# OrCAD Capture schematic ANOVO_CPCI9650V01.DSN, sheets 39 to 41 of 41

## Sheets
39 -ON BOARD DDRII B1: size D; title: ON BOARD DDRII B1
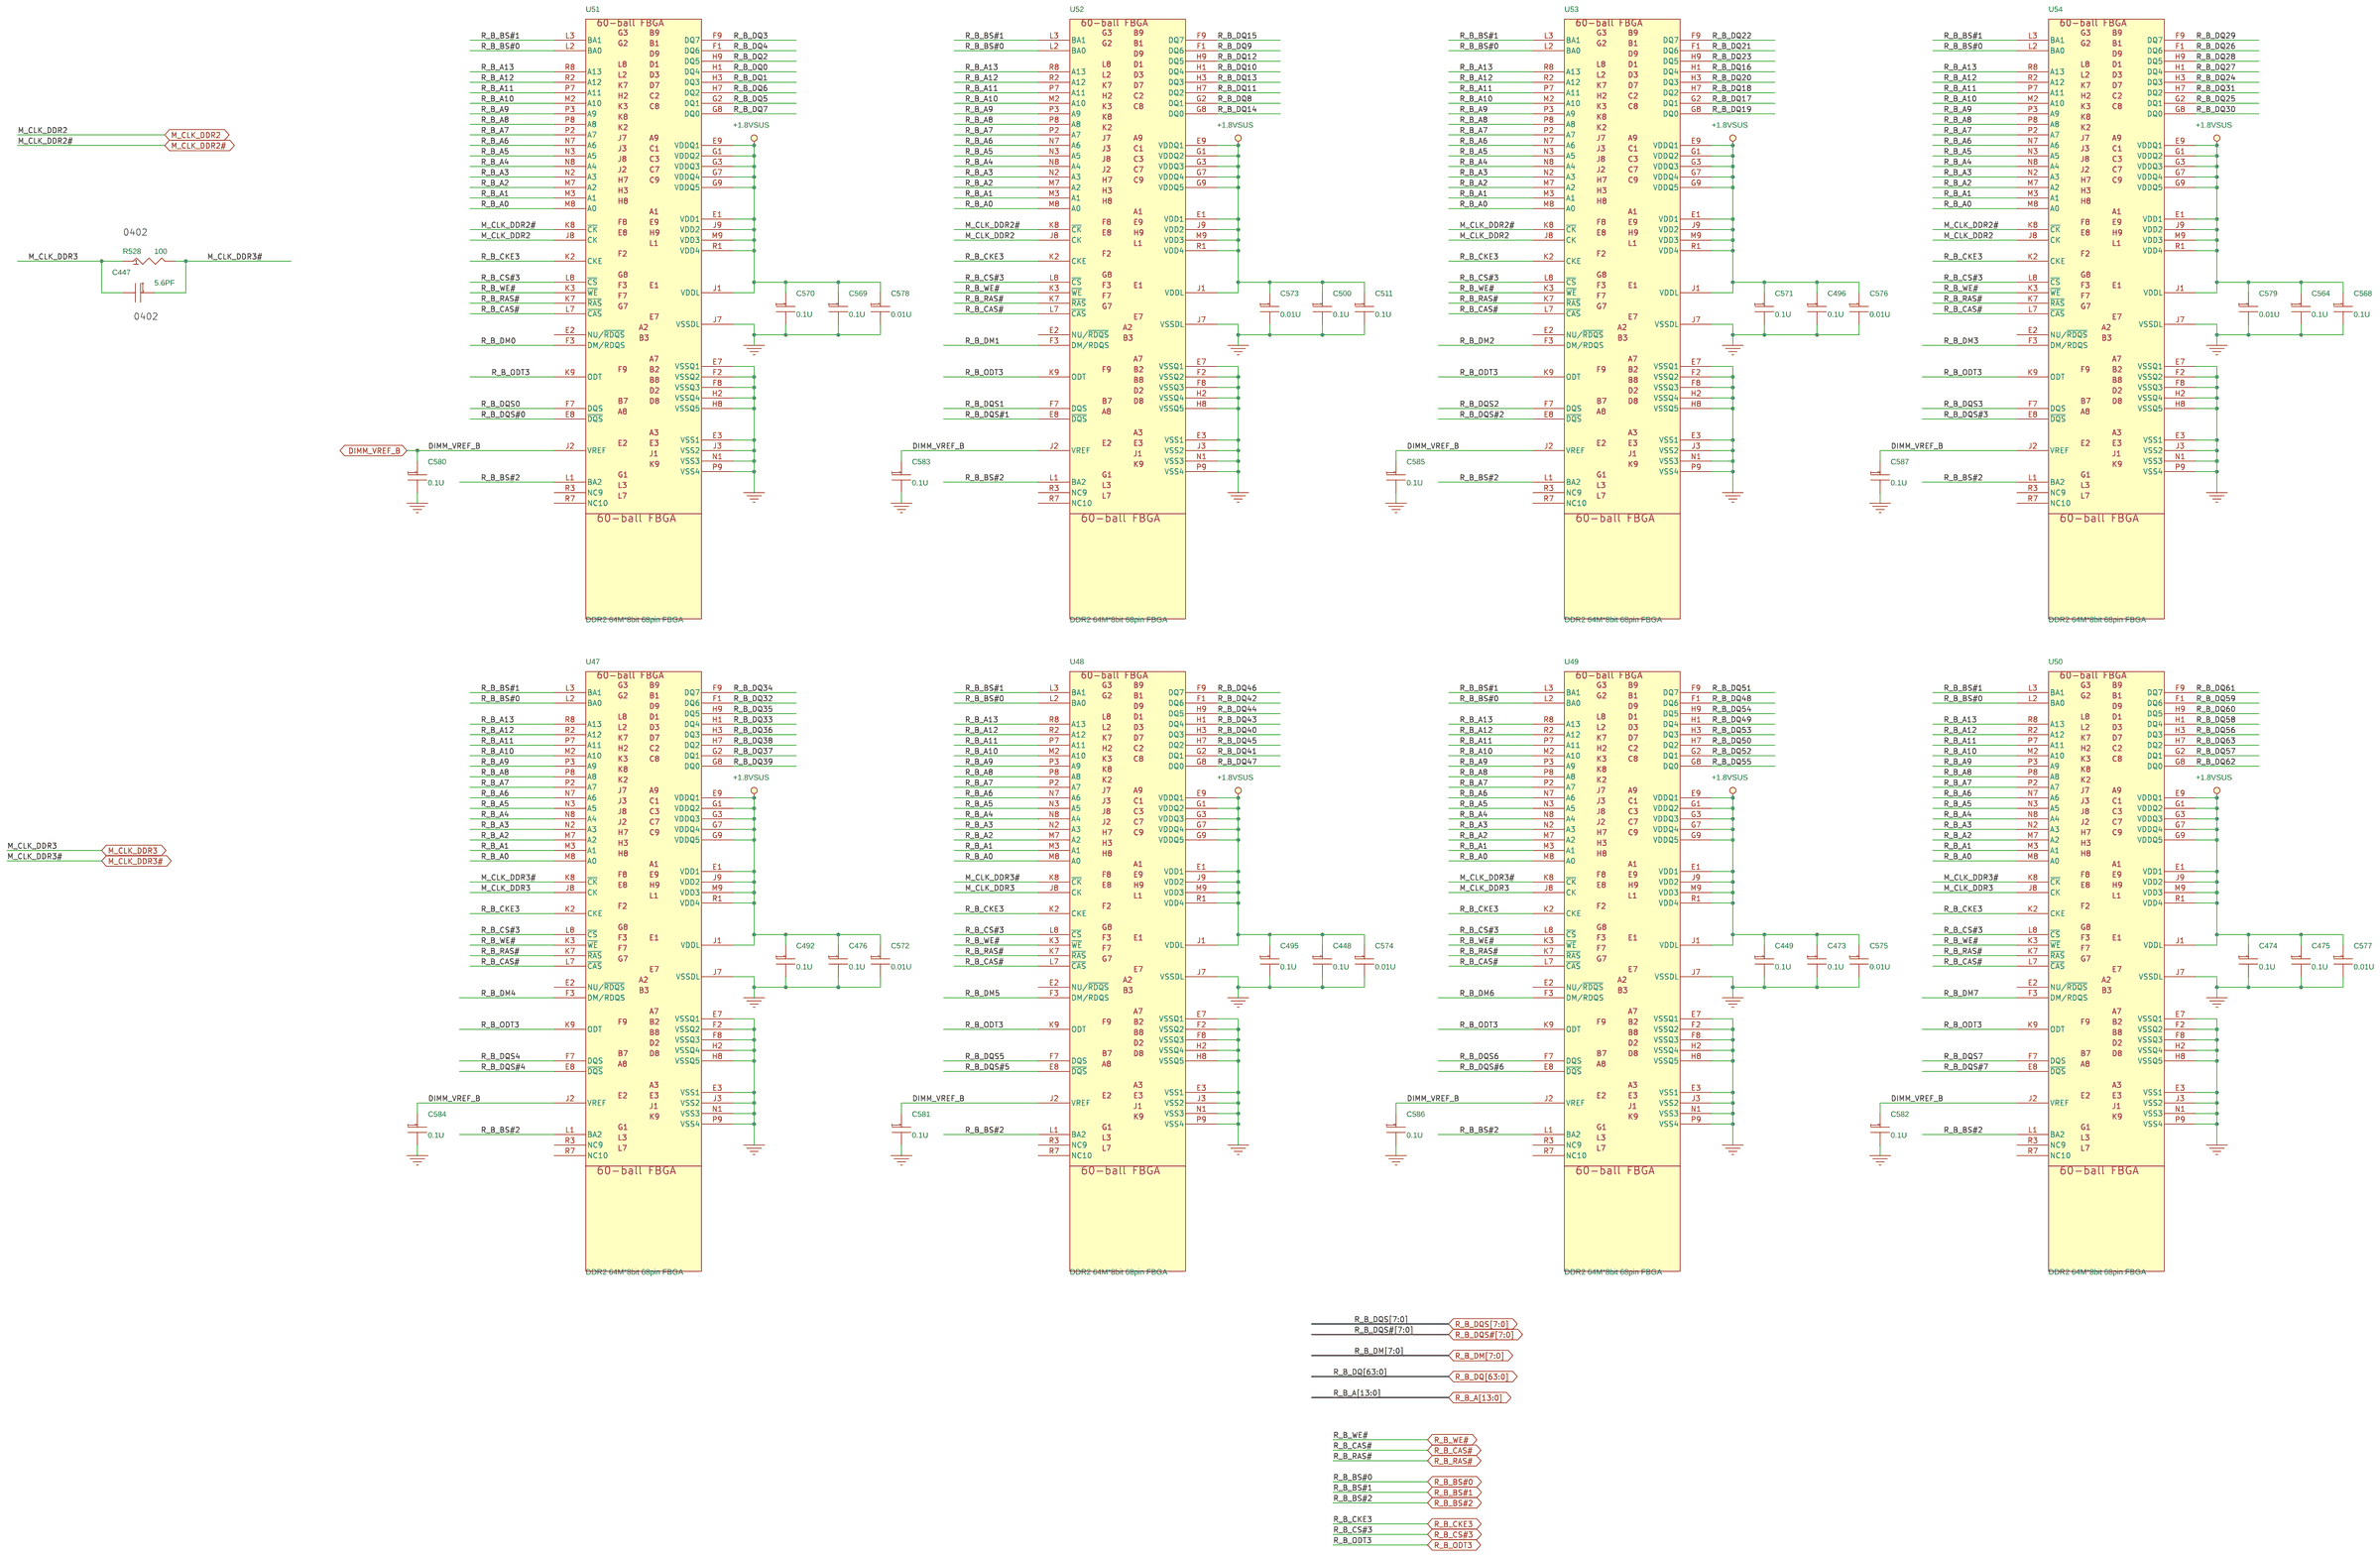
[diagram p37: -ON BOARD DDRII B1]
40 -Front IO: size C
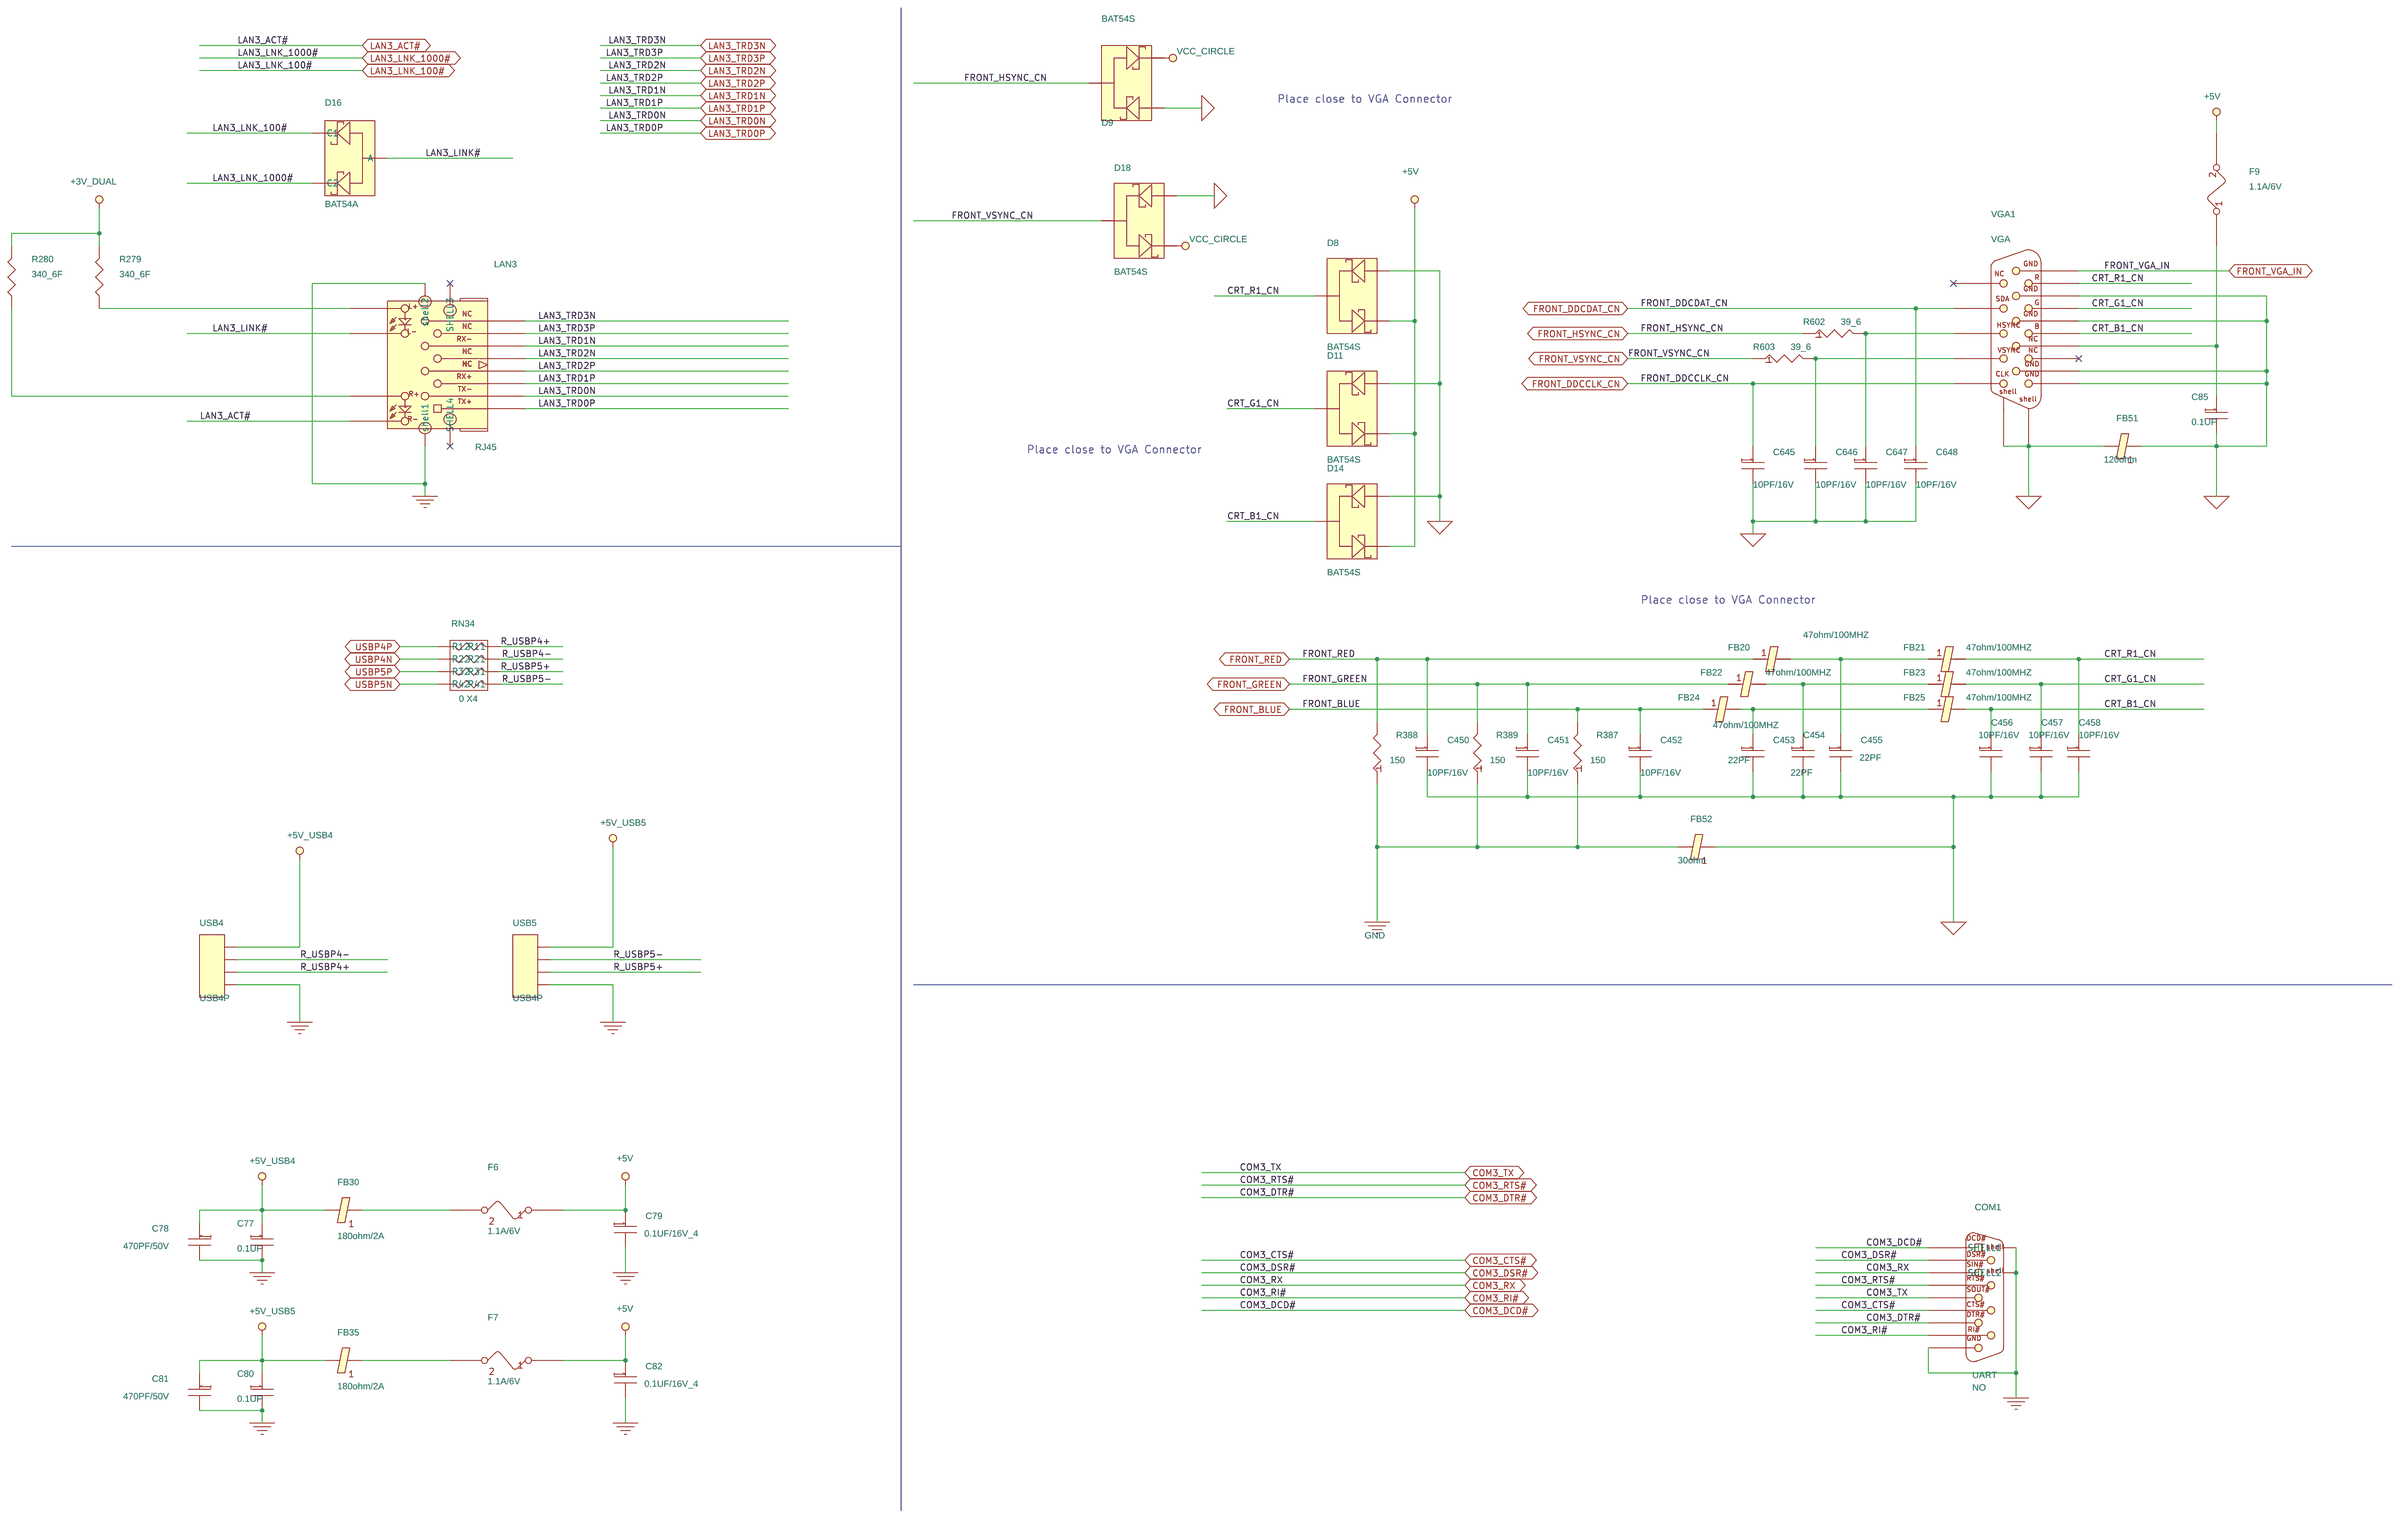
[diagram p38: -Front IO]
41 -GIGA LAN3: size C
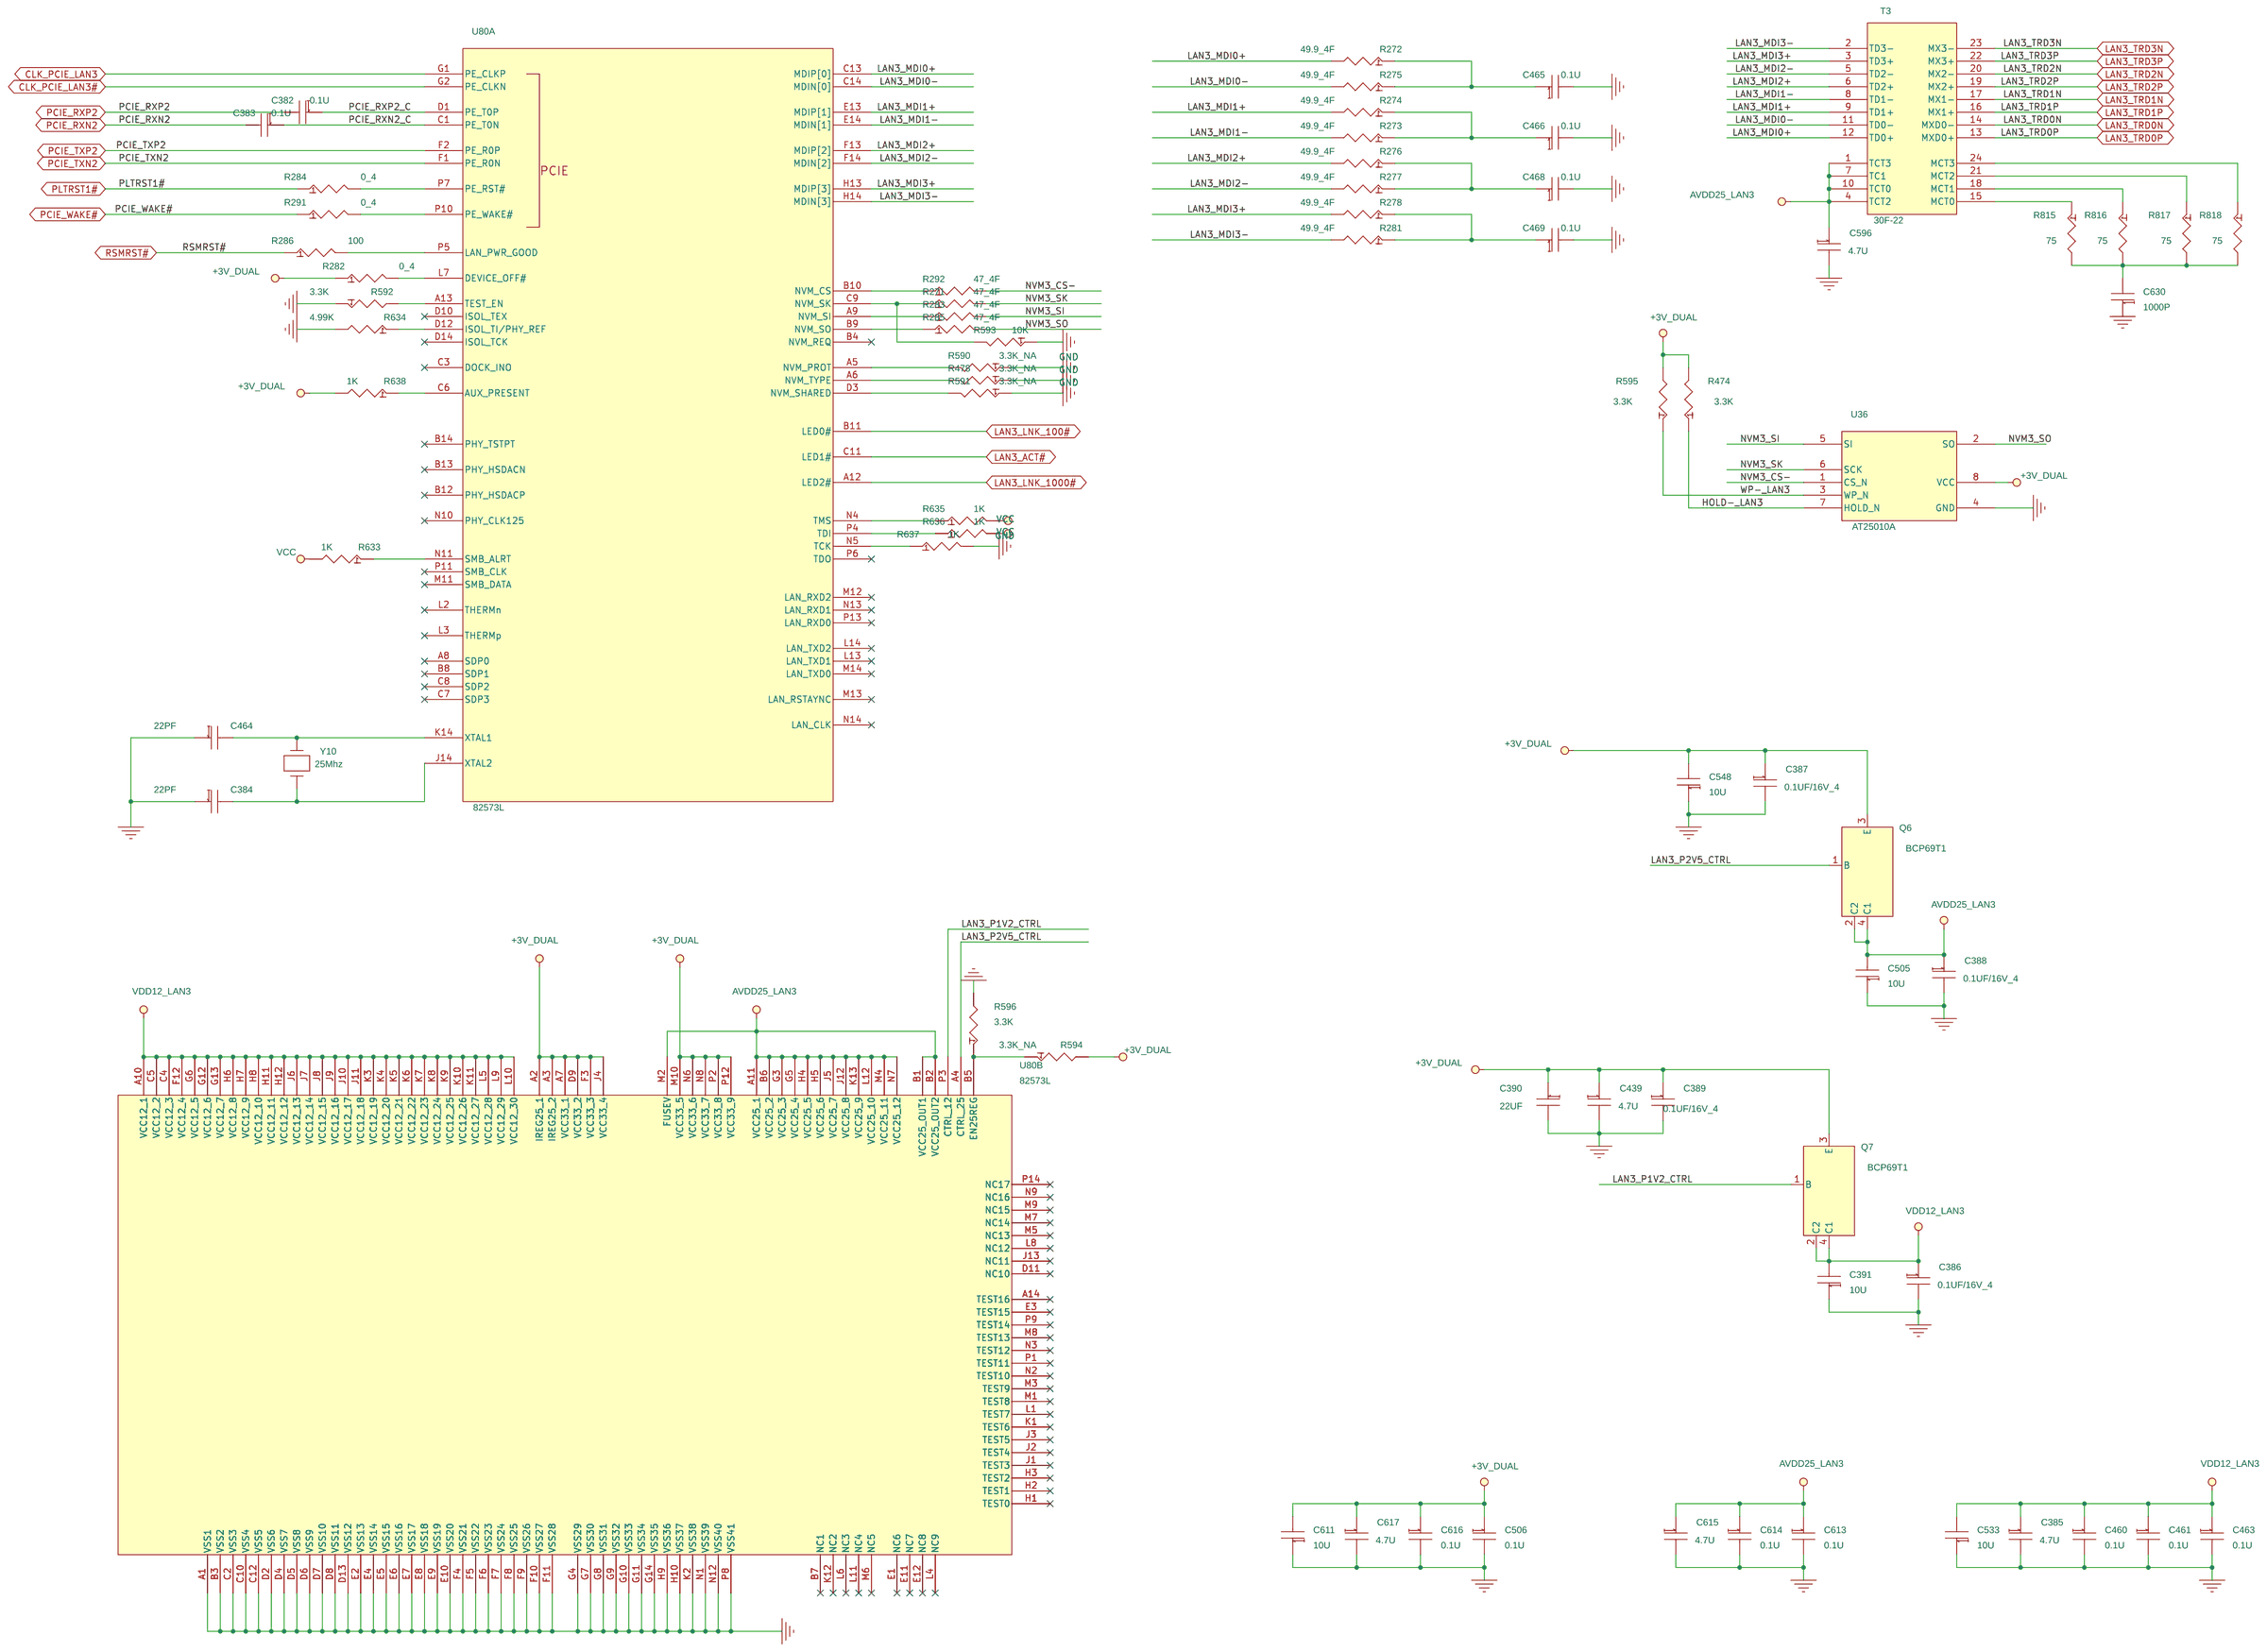
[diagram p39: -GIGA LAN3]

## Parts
sheet -Front IO
C77  0.1UF  [0402D]
C78  470PF/50V  [0402D]
C79  0.1UF/16V_4  [0402D]
C80  0.1UF  [0402D]
C81  470PF/50V  [0402D]
C82  0.1UF/16V_4  [0402D]
C85  0.1UF  [0402D]
C450  10PF/16V  [0402D]
C451  10PF/16V  [0402D]
C452  10PF/16V  [0402D]
C453  22PF  [0402D]
C454  22PF  [0402D]
C455  22PF  [0402D]
C456  10PF/16V  [0402D]
C457  10PF/16V  [0402D]
C458  10PF/16V  [0402D]
C645  10PF/16V  [0402D]
C646  10PF/16V  [0402D]
C647  10PF/16V  [0402D]
C648  10PF/16V  [0402D]
COM1  UART  [COM_X]
D8  BAT54S  [SOT23N_5]
D9  BAT54S  [SOT23N_5]
D11  BAT54S  [SOT23N_5]
D14  BAT54S  [SOT23N_5]
D16  BAT54A  [SOT23N_5]
D18  BAT54S  [SOT23N_5]
F6  1.1A/6V  [POLYSW_MINISMDC110]
F7  1.1A/6V  [POLYSW_MINISMDC110]
F9  1.1A/6V  [POLYSW_MINISMDC110]
FB20  47ohm/100MHZ  [0603D]
FB21  47ohm/100MHZ  [0603D]
FB22  47ohm/100MHZ  [0603D]
FB23  47ohm/100MHZ  [0603D]
FB24  47ohm/100MHZ  [0603D]
FB25  47ohm/100MHZ  [0603D]
FB30  180ohm/2A  [0805D]
FB35  180ohm/2A  [0805D]
FB51  120ohm  [0603D]
FB52  30ohm  [0805D]
LAN3  RJ45  [rj_45led_N]
R279  340_6F  [0603D]
R280  340_6F  [0603D]
R387  150  [0402D]
R388  150  [0402D]
R389  150  [0402D]
R602  39_6  [0603D]
R603  39_6  [0603D]
RN34  0 X4  [RP_8P4R_0804B]
USB4  USB4P  [usb_4p]
USB5  USB4P  [usb_4p]
VGA1  VGA  [conn_vga_thin]
sheet -GIGA LAN3
C382  0.1U  [0402D]
C383  0.1U  [0402D]
C384  22PF  [0402D]
C385  4.7U  [0805D]
C386  0.1UF/16V_4  [0402D]
C387  0.1UF/16V_4  [0402D]
C388  0.1UF/16V_4  [0402D]
C389  0.1UF/16V_4  [0402D]
C390  22UF  [0805D]
C391  10U  [0805D]
C439  4.7U  [0805D]
C460  0.1U  [0402D]
C461  0.1U  [0402D]
C463  0.1U  [0402D]
C464  22PF  [0402D]
C465  0.1U  [0402D]
C466  0.1U  [0402D]
C468  0.1U  [0402D]
C469  0.1U  [0402D]
C505  10U  [0805D]
C506  0.1U  [0402D]
C533  10U  [0805D]
C548  10U  [0805D]
C596  4.7U  [0805D]
C611  10U  [0805D]
C613  0.1U  [0402D]
C614  0.1U  [0402D]
C615  4.7U  [0805D]
C616  0.1U  [0402D]
C617  4.7U  [0805D]
C630  1000P  [1206A]
Q6  BCP69T1  [SOT223]
Q7  BCP69T1  [SOT223]
R271  47_4F  [0402D]
R272  49.9_4F  [0402D]
R273  49.9_4F  [0402D]
R274  49.9_4F  [0402D]
R275  49.9_4F  [0402D]
R276  49.9_4F  [0402D]
R277  49.9_4F  [0402D]
R278  49.9_4F  [0402D]
R281  49.9_4F  [0402D]
R282  0_4  [0402D]
R283  47_4F  [0402D]
R284  0_4  [0402D]
R285  47_4F  [0402D]
R286  100  [0402D]
R291  0_4  [0402D]
R292  47_4F  [0402D]
R474  3.3K  [0402D]
R478  3.3K_NA  [0402D]
R590  3.3K_NA  [0402D]
R591  3.3K_NA  [0402D]
R592  3.3K  [0402D]
R593  10K  [0402D]
R594  3.3K_NA  [0402D]
R595  3.3K  [0402D]
R596  3.3K  [0402D]
R633  1K  [0402D]
R634  4.99K  [0402D]
R635  1K  [0402D]
R636  1K  [0402D]
R637  1K  [0402D]
R638  1K  [0402D]
R815  75  [0402D]
R816  75  [0402D]
R817  75  [0402D]
R818  75  [0402D]
T3  30F-22  [XFMR_H500X]
U36  AT25010A  [SO8]
U80  82573L  [MBGA196]  (sections A,B)
Y10  25Mhz  [FA-365]
sheet -ON BOARD DDRII B1
C447  5.6PF  [0402D]
C448  0.1U  [0402D]
C449  0.1U  [0402D]
C473  0.1U  [0402D]
C474  0.1U  [0402D]
C475  0.1U  [0402D]
C476  0.1U  [0402D]
C492  0.1U  [0402D]
C495  0.1U  [0402D]
C496  0.1U  [0402D]
C500  0.1U  [0402D]
C511  0.1U  [0402D]
C564  0.1U  [0402D]
C568  0.1U  [0402D]
C569  0.1U  [0402D]
C570  0.1U  [0402D]
C571  0.1U  [0402D]
C572  0.01U  [0402D]
C573  0.01U  [0402D]
C574  0.01U  [0402D]
C575  0.01U  [0402D]
C576  0.01U  [0402D]
C577  0.01U  [0402D]
C578  0.01U  [0402D]
C579  0.01U  [0402D]
C580  0.1U  [0402D]
C581  0.1U  [0402D]
C582  0.1U  [0402D]
C583  0.1U  [0402D]
C584  0.1U  [0402D]
C585  0.1U  [0402D]
C586  0.1U  [0402D]
C587  0.1U  [0402D]
R528  100  [0402D]
U47  DDR2 64M*8bit 68pin FBGA  [fbga60]
U48  DDR2 64M*8bit 68pin FBGA  [fbga60]
U49  DDR2 64M*8bit 68pin FBGA  [fbga60]
U50  DDR2 64M*8bit 68pin FBGA  [fbga60]
U51  DDR2 64M*8bit 68pin FBGA  [fbga60]
U52  DDR2 64M*8bit 68pin FBGA  [fbga60]
U53  DDR2 64M*8bit 68pin FBGA  [fbga60]
U54  DDR2 64M*8bit 68pin FBGA  [fbga60]

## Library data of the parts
C77 C79 C80 C82 C85 C386-C389 C448 C449 C473-C476 C492 C495 C496 C500 C511 C564 C568-C571 C580-C587 = CAP_NP: ANOVO DESCRIPTION: CAP;0.1U ,16V ,+80-20% ,0402 ,Y5V ,SMT; ANOVO PART NUMBER: 272043104401; BACKSIDE: 0; Part Type: CCAP; SMT: YES
C78 C81 = CAP_NP: ANOVO DESCRIPTION: CAP;470P ,50V ,10% ,0402 ,X7R ,SMT; ANOVO PART NUMBER: 272045471201; BACKSIDE: 0; Part Type: CCAP
C450-C452 C456-C458 C645-C648 = CAP_NP: ANOVO DESCRIPTION: CAP;10P ,16V ,5% ,0402 ,NPO ,SMT; ANOVO PART NUMBER: 272043100101; BACKSIDE: 0; Part Type: CCAP; SMT: YES
C384 C453-C455 C464 = CAP_NP: ANOVO DESCRIPTION: CAP;22P ,50V ,5% ,0402 ,NPO ,SMT; ANOVO PART NUMBER: 272045220101; BACKSIDE: 0; Part Type: CCAP; SMT: YES
COM1 = DB9M: CONN DB9M R/A(MALE) PC99 FOXCONN; BACKCOMP: NO; BACKSIDE: NO; ID: 7; Manufacturer: FOXCONN; Part Number: 129000016; Part Type: CONN; ROOM: COM; SMT: NO; Sub Part: 129000000(CONN DB9M R/A(MALE) PC99 UNION); place : NO
D8 D9 D11 D14 D18 = BAT54S: ANOVO DESCRIPTION: DIODE;BAT54S,SCHOTTKY DIODE,SOT23; ANOVO PART NUMBER: 288100054021; BACKSIDE: 0; Part Type: SCHOTTKY; SMT: YES; Datasheet: \\Rdserver\norcocis\datasheet\DIODE\fairchild\BAT54.pdf
D16 = BAT54A: ANOVO DESCRIPTION: DIODE;BAT54A,SCHOTTKY DIODE,SOT23; ANOVO PART NUMBER: 288100054001
F6 F7 F9 = FUSE: ANOVO DESCRIPTION: FUSE,1.1A/6V,POLY SWITCH,1812,SMT; ANOVO PART NUMBER: 295000010009; BACKSIDE: 0; ROOM: DVI; SMT: YES
FB20-FB25 = FERRITE_BEAD: ANOVO DESCRIPTION: FERRITE CHIP;47 OHM/100MHZ,25%,0603, <0.05 ohm,600mA,SMT; ANOVO PART NUMBER: 273004703200; BACKSIDE: 0; Part Type: FERRITE BEAD; SMT: YES
FB30 FB35 = FERRITE_BEAD: ANOVO DESCRIPTION: FERRITE CHIP,180 OHM/100MHZ,2A,0805,SMT; ANOVO PART NUMBER: 273000180001; BACKSIDE: 0; Part Type: FERRITE BEAD; ROOM: IDE; SMT: YES
FB51 = FERRITE_BEAD: ANOVO DESCRIPTION: FERRITE CHIP;120 OHM/100MHZ,0603,600MA,SMT; ANOVO PART NUMBER: 273001213200; BACKSIDE: 0; Part Type: FERRITE BEAD; SMT: YES
FB52 = FERRITE_BEAD: ANOVO DESCRIPTION: FERRITE CHIP;30 OHM/100MHZ£¬0805£¬5A£¬SMT; ANOVO PART NUMBER: 273003005300; BACKSIDE: 0; Part Type: FERRITE BEAD; SMT: YES
LAN3 = RJ45_LED: LAN PORT RJ-45 WITH LED AMP; Part Number: 129000042; ROOM: LAN562; SMT: NO
R279 R280 = R_0: ANOVO DESCRIPTION: RES;340 ,1/10W ,1% ,0603 ,SMT; ANOVO PART NUMBER: 271071341101; Part Type: RESISTOR; Res: 348; SMT: YES; Tolerance: 1%; Watt: 1/10W
R387-R389 = R_v2: ANOVO DESCRIPTION: RES;150,1/16W,1%,0402,SMT; ANOVO PART NUMBER: 271040151101; BACKCOMP: NO; BACKSIDE: 0; Part Type: RESISTOR; SMT: YES
R602 R603 = R_v2: ANOVO DESCRIPTION: RES;39,1/10W ,5% ,0603 ,SMT; ANOVO PART NUMBER: 271071390301
RN34 = R_8P4R: network 0ohmx4 8pin smt +-5%; ANOVO DESCRIPTION: RP;0*4 ,8P ,1/16W ,5% ,0408,SMT; ANOVO PART NUMBER: 271590000301; Part Type: NETWORK; SMT: YES
USB4 USB5 = USB4P: Part Number: 131000013; SMT: NO
VGA1 = DB15_VGA: ANOVO DESCRIPTION: CON;DIP;D-SUB;Blue;15 Pins 3 ROWS;R/A;FOR VGA COMMON;PC99;Lotes; ANOVO PART NUMBER: 331430015000; BACKSIDE: 0; Part Type: CONN; SMT: NO
C382 C383 C460 C461 C463 C465 C466 C468 C469 C506 C613 C614 C616 = CAP_NP: ANOVO DESCRIPTION: CAP;0.1U ,16V ,10% ,0402 ,X7R ,SMT; ANOVO PART NUMBER: 272043104201; Part Type: CCAP
C385 C439 C596 C615 C617 = CAP_NP: ANOVO DESCRIPTION: CAP;4.7U ,10V ,+80-20% ,0805 ,Y5V ,SMT; ANOVO PART NUMBER: 272002475401; Part Type: CCAP
C390 = CAP_NP: ANOVO DESCRIPTION: CAP,22U ,CR,16V ,+80-20%,0805,Y5V,SMT,TAIYO; ANOVO PART NUMBER: 272003226401; BACKSIDE: 0; Part Type: CCAP; SMT: YES
C391 C505 C533 C548 C611 = CAP_NP: ANOVO DESCRIPTION: CAP;10U,10V,+80-20%,0805,Y5V,SMT; ANOVO PART NUMBER: 272002106401; Part Type: CCAP
C630 = CAP_NP: ANOVO DESCRIPTION: CAP;1000P ,1KV ,10% ,1206 ,X7R ,SMT; ANOVO PART NUMBER: 272431028011; Part Type: CCAP
Q6 Q7 = BCP69T: ANOVO DESCRIPTION: TRANS;BCP69T1,P-MOS,1A,SOT223,ON; ANOVO PART NUMBER: 288200069001; BACKSIDE: 0; Part Type: TRANSISTOR; SMT: YES
R271 R283 R285 R292 = R_v2: ANOVO DESCRIPTION: RES;47 ,1/16W ,5%, 0402 ,SMT; ANOVO PART NUMBER: 271040470301; BACKSIDE: 0; Part Type: RESISTOR; SMT: YES
R272-R278 R281 = R_v2: ANOVO DESCRIPTION: RES;49.9 ,1/16W ,1% ,0402 ,SMT; ANOVO PART NUMBER: 271040499811; BACKSIDE: 0; Part Type: RESISTOR; SMT: YES
R282 R284 R291 = R_v2: ANOVO DESCRIPTION: RES;0 ,1/16W ,5% ,0402 ,SMT; ANOVO PART NUMBER: 271040000301; BACKCOMP: YES; BACKSIDE: YES; ID: 0; Part Type: RESISTOR; SMT: YES
R286 = R_v2: ANOVO DESCRIPTION: RES;100 ,1/16W ,1% ,0402 ,SMT; ANOVO PART NUMBER: 271040101101; Part Type: RESISTOR
R474 R478 R590-R592 R594-R596 = R_v2: ANOVO DESCRIPTION: RES;3.3K ,1/16W ,5% ,0402 ,SMT; ANOVO PART NUMBER: 271040332301; Part Type: RESISTOR
R593 = R_v2: ANOVO DESCRIPTION: RES;10K ,1/16W ,5% ,0402 ,SMT; ANOVO PART NUMBER: 271040103301; BACKSIDE: 0; Part Type: RESISTOR; SMT: YES
R633 R635-R638 = R_v2: ANOVO DESCRIPTION: RES;1K ,1/16W ,1% ,0402 ,SMT; ANOVO PART NUMBER: 271040102101; Part Type: RESISTOR
R634 = R_v2: ANOVO DESCRIPTION: RES;4.99K ,1/16W ,1% ,0402 ,SMT; ANOVO PART NUMBER: 271040499111; POWER: 1/16W; Part Type: RESISTOR
R815-R818 = R_v2: ANOVO DESCRIPTION: RES;75 ,1/16W ,1% ,0402 ,SMT; ANOVO PART NUMBER: 271040750101; POWER: 1/16W; Part Type: RESISTOR
T3 = C33F22: ANOVO DESCRIPTION: TRANSFORMER,1000M/100M,30F-22,YDS; ANOVO PART NUMBER: 287303022001; BACKSIDE: 0; Part Type: TRANSFORMER; SMT: YES
U36 = 283476530001: ANOVO DESCRIPTION: IC;EEPROM,AT25010AN-10SU-2.7,128*8,2.7V-5.5V,I2C,SOIC,8P,M6010; ANOVO PART NUMBER: 283402501001
U80 = 284582573017_1: ANOVO DESCRIPTION: IC;PC82573L,GIGABIT ETHERNET CTLR,REV:SL8JD,BGA,196P; ANOVO PART NUMBER: 286308257302
Y10 = CRYSTAL: JM5; 8ND PART FIELD: BOT; ANOVO DESCRIPTION: Xtal;25MHz,+-30ppm,20pF,5032,2P,SMT; ANOVO PART NUMBER: 274022505400; Function Code: LAN; Part Description: XTAL SMD 25MHZ(+-30PPM5*3.2)7A25000058LF; Part Number: BG625000737; PartType: Crystal; Subsystem ID: LOM
C447 = CAP_NP: ANOVO DESCRIPTION: CAP;5.6P ,50V , 5% ,0402 ,NPO ,SMT; ANOVO PART NUMBER: 272045056101; BACKSIDE: 0; Part Type: CCAP; SMT: YES
C572-C579 = CAP_NP: ANOVO DESCRIPTION: CAP;0.01U ,16V ,10% ,0402 ,X7R ,SMT; ANOVO PART NUMBER: 272043103201; Part Type: CCAP
R528 = R_v2: ANOVO DESCRIPTION: RES;100 ,1/16W ,1% ,0402 ,SMT; ANOVO PART NUMBER: 271040101101
U47-U54 = DDR2_64M*8bit_60_5

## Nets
+1.8VSUS: C448.1 C449.1 C473.1 C474.1 C475.1 C476.1 C492.1 C495.1 C496.1 C500.1 C511.1 C564.1 C568.1 C569.1 C570.1 C571.1 C572.1 C573.1 C574.1 C575.1 C576.1 C577.1 C578.1 C579.1 U47.E1(VDD1) U47.E9(VDDQ1) U47.G1(VDDQ2) U47.G3(VDDQ3) U47.G7(VDDQ4) U47.G9(VDDQ5) U47.J1(VDDL) U47.J9(VDD2) U47.M9(VDD3) U47.R1(VDD4) U48.E1(VDD1) U48.E9(VDDQ1) U48.G1(VDDQ2) U48.G3(VDDQ3) U48.G7(VDDQ4) U48.G9(VDDQ5) U48.J1(VDDL) U48.J9(VDD2) U48.M9(VDD3) U48.R1(VDD4) U49.E1(VDD1) U49.E9(VDDQ1) U49.G1(VDDQ2) U49.G3(VDDQ3) U49.G7(VDDQ4) U49.G9(VDDQ5) U49.J1(VDDL) U49.J9(VDD2) U49.M9(VDD3) U49.R1(VDD4) U50.E1(VDD1) U50.E9(VDDQ1) U50.G1(VDDQ2) U50.G3(VDDQ3) U50.G7(VDDQ4) U50.G9(VDDQ5) U50.J1(VDDL) U50.J9(VDD2) U50.M9(VDD3) U50.R1(VDD4) U51.E1(VDD1) U51.E9(VDDQ1) U51.G1(VDDQ2) U51.G3(VDDQ3) U51.G7(VDDQ4) U51.G9(VDDQ5) U51.J1(VDDL) U51.J9(VDD2) U51.M9(VDD3) U51.R1(VDD4) U52.E1(VDD1) U52.E9(VDDQ1) U52.G1(VDDQ2) U52.G3(VDDQ3) U52.G7(VDDQ4) U52.G9(VDDQ5) U52.J1(VDDL) U52.J9(VDD2) U52.M9(VDD3) U52.R1(VDD4) U53.E1(VDD1) U53.E9(VDDQ1) U53.G1(VDDQ2) U53.G3(VDDQ3) U53.G7(VDDQ4) U53.G9(VDDQ5) U53.J1(VDDL) U53.J9(VDD2) U53.M9(VDD3) U53.R1(VDD4) U54.E1(VDD1) U54.E9(VDDQ1) U54.G1(VDDQ2) U54.G3(VDDQ3) U54.G7(VDDQ4) U54.G9(VDDQ5) U54.J1(VDDL) U54.J9(VDD2) U54.M9(VDD3) U54.R1(VDD4) ; also on sheet 9 11 12 14 21 32 33 38
+3V: R633.2 R635.2 R636.2 ; also on sheet 4 9 10 12 15 16 17 18 19 20 21 22 23 24 25 26 27 28 31 32 34 35
+3V_DUAL: C387.1 C389.1 C390.1 C439.1 C506.1 C548.2 C611.2 C616.1 C617.1 Q6.3(E) Q7.3(E) R279.2 R280.2 R282.1 R474.2 R594.2 R595.2 R638.2 U36.8(VCC) U80.A2(IREG25_1) U80.A3(IREG25_2) U80.A7(VCC33_1) U80.D9(VCC33_2) U80.F3(VCC33_3) U80.J4(VCC33_4) U80.M10(VCC33_5) U80.N6(VCC33_6) U80.N8(VCC33_7) U80.P2(VCC33_8) U80.P12(VCC33_9) ; also on sheet 14 15 16 17 18 19 20 21 26 31 33 34 38
+5V: C79.1 C82.1 D8.2 D9.2 D11.2 D14.2 D18.2 F6.1 F7.1 F9.2 ; also on sheet 18 21 22 23 24 25 26 27 29 30 31 32 33 34 35
+5V_USB4: C77.1 C78.1 FB30.2 USB4.1
+5V_USB5: C80.1 C81.1 FB35.2 USB5.1
AVDD25_LAN3: C388.1 C505.2 C596.1 C613.1 C614.1 C615.1 Q6.2(C2) Q6.4(C1) T3.1(TCT3) T3.4(TCT2) T3.7(TC1) T3.10(TCT0) U80.A11(VCC25_1) U80.B1(VCC25_OUT1) U80.B2(VCC25_OUT2) U80.B6(VCC25_2) U80.G3(VCC25_3) U80.G5(VCC25_4) U80.H4(VCC25_5) U80.H5(VCC25_6) U80.J5(VCC25_7) U80.J12(VCC25_8) U80.K13(VCC25_9) U80.L12(VCC25_10) U80.M2(FUSEV) U80.M4(VCC25_11) U80.N7(VCC25_12)
GND: C77.2 C78.2 C79.2 C80.2 C81.2 C82.2 C384.1 C385.2 C386.2 C387.2 C388.2 C389.2 C390.2 C391.1 C439.2 C448.2 C449.2 C460.2 C461.2 C463.2 C464.1 C465.2 C466.2 C468.2 C469.2 C473.2 C474.2 C475.2 C476.2 C492.2 C495.2 C496.2 C500.2 C505.1 C506.2 C511.2 C533.1 C548.1 C564.2 C568.2 C569.2 C570.2 C571.2 C572.2 C573.2 C574.2 C575.2 C576.2 C577.2 C578.2 C579.2 C580.2 C581.2 C582.2 C583.2 C584.2 C585.2 C586.2 C587.2 C596.2 C611.1 C613.2 C614.2 C615.2 C616.2 C617.2 C630.1 COM1.5 COM1.10(SHELL2) COM1.11(SHELL1) FB52.2 LAN3.13(shell1) LAN3.14(shell2) R387.1 R388.1 R389.1 R478.1 R590.1 R591.1 R592.1 R593.1 R596.2 R634.2 R637.2 U36.4(GND) U47.E3(VSS1) U47.E7(VSSQ1) U47.F2(VSSQ2) U47.F8(VSSQ3) U47.H2(VSSQ4) U47.H8(VSSQ5) U47.J3(VSS2) U47.J7(VSSDL) U47.N1(VSS3) U47.P9(VSS4) U48.E3(VSS1) U48.E7(VSSQ1) U48.F2(VSSQ2) U48.F8(VSSQ3) U48.H2(VSSQ4) U48.H8(VSSQ5) U48.J3(VSS2) U48.J7(VSSDL) U48.N1(VSS3) U48.P9(VSS4) U49.E3(VSS1) U49.E7(VSSQ1) U49.F2(VSSQ2) U49.F8(VSSQ3) U49.H2(VSSQ4) U49.H8(VSSQ5) U49.J3(VSS2) U49.J7(VSSDL) U49.N1(VSS3) U49.P9(VSS4) U50.E3(VSS1) U50.E7(VSSQ1) U50.F2(VSSQ2) U50.F8(VSSQ3) U50.H2(VSSQ4) U50.H8(VSSQ5) U50.J3(VSS2) U50.J7(VSSDL) U50.N1(VSS3) U50.P9(VSS4) U51.E3(VSS1) U51.E7(VSSQ1) U51.F2(VSSQ2) U51.F8(VSSQ3) U51.H2(VSSQ4) U51.H8(VSSQ5) U51.J3(VSS2) U51.J7(VSSDL) U51.N1(VSS3) U51.P9(VSS4) U52.E3(VSS1) U52.E7(VSSQ1) U52.F2(VSSQ2) U52.F8(VSSQ3) U52.H2(VSSQ4) U52.H8(VSSQ5) U52.J3(VSS2) U52.J7(VSSDL) U52.N1(VSS3) U52.P9(VSS4) U53.E3(VSS1) U53.E7(VSSQ1) U53.F2(VSSQ2) U53.F8(VSSQ3) U53.H2(VSSQ4) U53.H8(VSSQ5) U53.J3(VSS2) U53.J7(VSSDL) U53.N1(VSS3) U53.P9(VSS4) U54.E3(VSS1) U54.E7(VSSQ1) U54.F2(VSSQ2) U54.F8(VSSQ3) U54.H2(VSSQ4) U54.H8(VSSQ5) U54.J3(VSS2) U54.J7(VSSDL) U54.N1(VSS3) U54.P9(VSS4) U80.A1(VSS1) U80.B3(VSS2) U80.C2(VSS3) U80.C10(VSS4) U80.C12(VSS5) U80.D2(VSS6) U80.D4(VSS7) U80.D5(VSS8) U80.D6(VSS9) U80.D7(VSS10) U80.D8(VSS11) U80.D13(VSS12) U80.E2(VSS13) U80.E4(VSS14) U80.E5(VSS15) U80.E6(VSS16) U80.E7(VSS17) U80.E8(VSS18) U80.E9(VSS19) U80.E10(VSS20) U80.F4(VSS21) U80.F5(VSS22) U80.F6(VSS23) U80.F7(VSS24) U80.F8(VSS25) U80.F9(VSS26) U80.F10(VSS27) U80.F11(VSS28) U80.G4(VSS29) U80.G7(VSS30) U80.G8(VSS31) U80.G9(VSS32) U80.G10(VSS33) U80.G11(VSS34) U80.G14(VSS35) U80.H9(VSS36) U80.H10(VSS37) U80.K2(VSS38) U80.N1(VSS39) U80.N12(VSS40) U80.P8(VSS41) USB4.4 USB5.4 ; also on sheet 4 5 6 7 9 10 11 12 13 14 15 16 17 18 19 20 21 22 23 24 25 26 27 28 29 30 31 32 33 34 35 36 37 38
GND_IO: D8.1 D9.1 D11.1 D14.1 D18.1 FB51.2 VGA1.16 VGA1.17
GND_V: C85.2 C450.2 C451.2 C452.2 C453.2 C454.2 C455.2 C456.2 C457.2 C458.2 C645.2 C646.2 C647.2 C648.2 FB51.1 FB52.1 VGA1.5 VGA1.7 VGA1.8 VGA1.10
VDD12_LAN3: C385.1 C386.1 C391.2 C460.1 C461.1 C463.1 C533.2 Q7.2(C2) Q7.4(C1) U80.A10(VCC12_1) U80.C4(VCC12_3) U80.C5(VCC12_2) U80.F12(VCC12_4) U80.G6(VCC12_5) U80.G12(VCC12_6) U80.G13(VCC12_7) U80.H6(VCC12_8) U80.H7(VCC12_9) U80.H8(VCC12_10) U80.H11(VCC12_11) U80.H12(VCC12_12) U80.J6(VCC12_13) U80.J7(VCC12_14) U80.J8(VCC12_15) U80.J9(VCC12_16) U80.J10(VCC12_17) U80.J11(VCC12_18) U80.K3(VCC12_19) U80.K4(VCC12_20) U80.K5(VCC12_21) U80.K6(VCC12_22) U80.K7(VCC12_23) U80.K8(VCC12_24) U80.K9(VCC12_25) U80.K10(VCC12_26) U80.K11(VCC12_27) U80.L5(VCC12_28) U80.L9(VCC12_29) U80.L10(VCC12_30)
CLK_PCIE_LAN3: U80.G1(PE_CLKP) ; also on sheet 4
CLK_PCIE_LAN3#: U80.G2(PE_CLKN) ; also on sheet 4
COM3_CTS#: COM1.8 ; also on sheet 22
COM3_DCD#: COM1.1 ; also on sheet 22
COM3_DSR#: COM1.6 ; also on sheet 22
COM3_DTR#: COM1.4 ; also on sheet 22
COM3_RI#: COM1.9 ; also on sheet 22
COM3_RTS#: COM1.7 ; also on sheet 22
COM3_RX: COM1.2 ; also on sheet 22
COM3_TX: COM1.3 ; also on sheet 22
CRT_B1_CN: C456.1 D14.3 FB25.2 VGA1.3
CRT_G1_CN: C457.1 D11.3 FB23.2 VGA1.2
CRT_R1_CN: C458.1 D8.3 FB21.2 VGA1.1
DIMM_VREF_B: C580.1 C581.1 C582.1 C583.1 C584.1 C585.1 C586.1 C587.1 U47.J2(VREF) U48.J2(VREF) U49.J2(VREF) U50.J2(VREF) U51.J2(VREF) U52.J2(VREF) U53.J2(VREF) U54.J2(VREF) ; also on sheet 38
FRONT_BLUE: C452.1 FB24.1 R387.2 ; also on sheet 26
FRONT_DDCCLK_CN: C645.1 VGA1.15 ; also on sheet 26
FRONT_DDCDAT_CN: C648.1 VGA1.12 ; also on sheet 26
FRONT_GREEN: C451.1 FB22.1 R389.2 ; also on sheet 26
FRONT_HSYNC_CN: D9.3 R602.1 ; also on sheet 26
FRONT_RED: C450.1 FB20.1 R388.2 ; also on sheet 26
FRONT_VGA_IN: VGA1.6 ; also on sheet 22
FRONT_VSYNC_CN: D18.3 R603.1 ; also on sheet 26
HOLD-_LAN3: R474.1 U36.7(HOLD_N)
LAN3_ACT#: LAN3.12 U80.C11(LED1#)
LAN3_LINK#: D16.3(A) LAN3.10
LAN3_LNK_100#: D16.1(C1) U80.B11(LED0#)
LAN3_LNK_1000#: D16.2(C2) U80.A12(LED2#)
LAN3_MDI0+: R272.2 T3.12(TD0+) U80.C13(MDIP[0])
LAN3_MDI0-: R275.2 T3.11(TD0-) U80.C14(MDIN[0])
LAN3_MDI1+: R274.2 T3.9(TD1+) U80.E13(MDIP[1])
LAN3_MDI1-: R273.2 T3.8(TD1-) U80.E14(MDIN[1])
LAN3_MDI2+: R276.2 T3.6(TD2+) U80.F13(MDIP[2])
LAN3_MDI2-: R277.2 T3.5(TD2-) U80.F14(MDIN[2])
LAN3_MDI3+: R278.2 T3.3(TD3+) U80.H13(MDIP[3])
LAN3_MDI3-: R281.2 T3.2(TD3-) U80.H14(MDIN[3])
LAN3_P1V2_CTRL: Q7.1(B) U80.P3(CTRL_12)
LAN3_P2V5_CTRL: Q6.1(B) U80.A4(CTRL_25)
LAN3_TRD0N: LAN3.2 T3.14(MXD0-)
LAN3_TRD0P: LAN3.1 T3.13(MXD0+)
LAN3_TRD1N: LAN3.6 T3.17(MX1-)
LAN3_TRD1P: LAN3.3 T3.16(MX1+)
LAN3_TRD2N: LAN3.5 T3.20(MX2-)
LAN3_TRD2P: LAN3.4 T3.19(MX2+)
LAN3_TRD3N: LAN3.8 T3.23(MX3-)
LAN3_TRD3P: LAN3.7 T3.22(MX3+)
M_CLK_DDR2: U51.J8(CK) U52.J8(CK) U53.J8(CK) U54.J8(CK) ; also on sheet 9 38
M_CLK_DDR2#: U51.K8(~{CK}) U52.K8(~{CK}) U53.K8(~{CK}) U54.K8(~{CK}) ; also on sheet 9 38
M_CLK_DDR3: C447.2 R528.1 U47.J8(CK) U48.J8(CK) U49.J8(CK) U50.J8(CK) ; also on sheet 9 38
M_CLK_DDR3#: C447.1 R528.2 U47.K8(~{CK}) U48.K8(~{CK}) U49.K8(~{CK}) U50.K8(~{CK}) ; also on sheet 9 38
NVM3_CS-: R292.2 U36.1(CS_N)
NVM3_SI: R283.2 U36.5(SI)
NVM3_SK: R271.2 U36.6(SCK)
NVM3_SO: R285.2 U36.2(SO)
PCIE_RXN2: C383.2 ; also on sheet 16
PCIE_RXN2_C: C383.1 U80.C1(PE_T0N)
PCIE_RXP2: C382.2 ; also on sheet 16
PCIE_RXP2_C: C382.1 U80.D1(PE_T0P)
PCIE_TXN2: U80.F1(PE_R0N) ; also on sheet 16
PCIE_TXP2: U80.F2(PE_R0P) ; also on sheet 16
PCIE_WAKE#: R291.1 ; also on sheet 17 19 20
PLTRST1#: R284.1 ; also on sheet 16
R_B_A0: U47.M8(A0) U48.M8(A0) U49.M8(A0) U50.M8(A0) U51.M8(A0) U52.M8(A0) U53.M8(A0) U54.M8(A0) ; also on sheet 37 38
R_B_A1: U47.M3(A1) U48.M3(A1) U49.M3(A1) U50.M3(A1) U51.M3(A1) U52.M3(A1) U53.M3(A1) U54.M3(A1) ; also on sheet 37 38
R_B_A2: U47.M7(A2) U48.M7(A2) U49.M7(A2) U50.M7(A2) U51.M7(A2) U52.M7(A2) U53.M7(A2) U54.M7(A2) ; also on sheet 37 38
R_B_A3: U47.N2(A3) U48.N2(A3) U49.N2(A3) U50.N2(A3) U51.N2(A3) U52.N2(A3) U53.N2(A3) U54.N2(A3) ; also on sheet 37 38
R_B_A4: U47.N8(A4) U48.N8(A4) U49.N8(A4) U50.N8(A4) U51.N8(A4) U52.N8(A4) U53.N8(A4) U54.N8(A4) ; also on sheet 37 38
R_B_A5: U47.N3(A5) U48.N3(A5) U49.N3(A5) U50.N3(A5) U51.N3(A5) U52.N3(A5) U53.N3(A5) U54.N3(A5) ; also on sheet 37 38
R_B_A6: U47.N7(A6) U48.N7(A6) U49.N7(A6) U50.N7(A6) U51.N7(A6) U52.N7(A6) U53.N7(A6) U54.N7(A6) ; also on sheet 37 38
R_B_A7: U47.P2(A7) U48.P2(A7) U49.P2(A7) U50.P2(A7) U51.P2(A7) U52.P2(A7) U53.P2(A7) U54.P2(A7) ; also on sheet 37 38
R_B_A8: U47.P8(A8) U48.P8(A8) U49.P8(A8) U50.P8(A8) U51.P8(A8) U52.P8(A8) U53.P8(A8) U54.P8(A8) ; also on sheet 37 38
R_B_A9: U47.P3(A9) U48.P3(A9) U49.P3(A9) U50.P3(A9) U51.P3(A9) U52.P3(A9) U53.P3(A9) U54.P3(A9) ; also on sheet 37 38
R_B_A10: U47.M2(A10) U48.M2(A10) U49.M2(A10) U50.M2(A10) U51.M2(A10) U52.M2(A10) U53.M2(A10) U54.M2(A10) ; also on sheet 37 38
R_B_A11: U47.P7(A11) U48.P7(A11) U49.P7(A11) U50.P7(A11) U51.P7(A11) U52.P7(A11) U53.P7(A11) U54.P7(A11) ; also on sheet 37 38
R_B_A12: U47.R2(A12) U48.R2(A12) U49.R2(A12) U50.R2(A12) U51.R2(A12) U52.R2(A12) U53.R2(A12) U54.R2(A12) ; also on sheet 37 38
R_B_A13: U47.R8(A13) U48.R8(A13) U49.R8(A13) U50.R8(A13) U51.R8(A13) U52.R8(A13) U53.R8(A13) U54.R8(A13) ; also on sheet 37 38
R_B_BS#0: U47.L2(BA0) U48.L2(BA0) U49.L2(BA0) U50.L2(BA0) U51.L2(BA0) U52.L2(BA0) U53.L2(BA0) U54.L2(BA0) ; also on sheet 37 38
R_B_BS#1: U47.L3(BA1) U48.L3(BA1) U49.L3(BA1) U50.L3(BA1) U51.L3(BA1) U52.L3(BA1) U53.L3(BA1) U54.L3(BA1) ; also on sheet 37 38
R_B_BS#2: U47.L1(BA2) U48.L1(BA2) U49.L1(BA2) U50.L1(BA2) U51.L1(BA2) U52.L1(BA2) U53.L1(BA2) U54.L1(BA2) ; also on sheet 37 38
R_B_CAS#: U47.L7(~{CAS}) U48.L7(~{CAS}) U49.L7(~{CAS}) U50.L7(~{CAS}) U51.L7(~{CAS}) U52.L7(~{CAS}) U53.L7(~{CAS}) U54.L7(~{CAS}) ; also on sheet 37 38
R_B_CKE3: U47.K2(CKE) U48.K2(CKE) U49.K2(CKE) U50.K2(CKE) U51.K2(CKE) U52.K2(CKE) U53.K2(CKE) U54.K2(CKE) ; also on sheet 37
R_B_CS#3: U47.L8(~{CS}) U48.L8(~{CS}) U49.L8(~{CS}) U50.L8(~{CS}) U51.L8(~{CS}) U52.L8(~{CS}) U53.L8(~{CS}) U54.L8(~{CS}) ; also on sheet 37
R_B_DM0: U51.F3(DM/RDQS) ; also on sheet 38
R_B_DM1: U52.F3(DM/RDQS) ; also on sheet 38
R_B_DM2: U53.F3(DM/RDQS) ; also on sheet 38
R_B_DM3: U54.F3(DM/RDQS) ; also on sheet 38
R_B_DM4: U47.F3(DM/RDQS) ; also on sheet 38
R_B_DM5: U48.F3(DM/RDQS) ; also on sheet 38
R_B_DM6: U49.F3(DM/RDQS) ; also on sheet 38
R_B_DM7: U50.F3(DM/RDQS) ; also on sheet 38
R_B_DQ0: U51.H1(DQ4) ; also on sheet 37 38
R_B_DQ1: U51.H3(DQ3) ; also on sheet 37 38
R_B_DQ2: U51.H9(DQ5) ; also on sheet 37 38
R_B_DQ3: U51.F9(DQ7) ; also on sheet 37 38
R_B_DQ4: U51.F1(DQ6) ; also on sheet 37 38
R_B_DQ5: U51.G2(DQ1) ; also on sheet 37 38
R_B_DQ6: U51.H7(DQ2) ; also on sheet 37 38
R_B_DQ7: U51.G8(DQ0) ; also on sheet 37 38
R_B_DQ8: U52.G2(DQ1) ; also on sheet 37 38
R_B_DQ9: U52.F1(DQ6) ; also on sheet 37 38
R_B_DQ10: U52.H1(DQ4) ; also on sheet 37 38
R_B_DQ11: U52.H7(DQ2) ; also on sheet 37 38
R_B_DQ12: U52.H9(DQ5) ; also on sheet 37 38
R_B_DQ13: U52.H3(DQ3) ; also on sheet 37 38
R_B_DQ14: U52.G8(DQ0) ; also on sheet 37 38
R_B_DQ15: U52.F9(DQ7) ; also on sheet 37 38
R_B_DQ16: U53.H1(DQ4) ; also on sheet 37 38
R_B_DQ17: U53.G2(DQ1) ; also on sheet 37 38
R_B_DQ18: U53.H7(DQ2) ; also on sheet 37 38
R_B_DQ19: U53.G8(DQ0) ; also on sheet 37 38
R_B_DQ20: U53.H3(DQ3) ; also on sheet 37 38
R_B_DQ21: U53.F1(DQ6) ; also on sheet 37 38
R_B_DQ22: U53.F9(DQ7) ; also on sheet 37 38
R_B_DQ23: U53.H9(DQ5) ; also on sheet 37 38
R_B_DQ24: U54.H3(DQ3) ; also on sheet 37 38
R_B_DQ25: U54.G2(DQ1) ; also on sheet 37 38
R_B_DQ26: U54.F1(DQ6) ; also on sheet 37 38
R_B_DQ27: U54.H1(DQ4) ; also on sheet 37 38
R_B_DQ28: U54.H9(DQ5) ; also on sheet 37 38
R_B_DQ29: U54.F9(DQ7) ; also on sheet 37 38
R_B_DQ30: U54.G8(DQ0) ; also on sheet 37 38
R_B_DQ31: U54.H7(DQ2) ; also on sheet 37 38
R_B_DQ32: U47.F1(DQ6) ; also on sheet 37 38
R_B_DQ33: U47.H1(DQ4) ; also on sheet 37 38
R_B_DQ34: U47.F9(DQ7) ; also on sheet 37 38
R_B_DQ35: U47.H9(DQ5) ; also on sheet 37 38
R_B_DQ36: U47.H3(DQ3) ; also on sheet 37 38
R_B_DQ37: U47.G2(DQ1) ; also on sheet 37 38
R_B_DQ38: U47.H7(DQ2) ; also on sheet 37 38
R_B_DQ39: U47.G8(DQ0) ; also on sheet 37 38
R_B_DQ40: U48.H3(DQ3) ; also on sheet 37 38
R_B_DQ41: U48.G2(DQ1) ; also on sheet 37 38
R_B_DQ42: U48.F1(DQ6) ; also on sheet 37 38
R_B_DQ43: U48.H1(DQ4) ; also on sheet 37 38
R_B_DQ44: U48.H9(DQ5) ; also on sheet 37 38
R_B_DQ45: U48.H7(DQ2) ; also on sheet 37 38
R_B_DQ46: U48.F9(DQ7) ; also on sheet 37 38
R_B_DQ47: U48.G8(DQ0) ; also on sheet 37 38
R_B_DQ48: U49.F1(DQ6) ; also on sheet 37 38
R_B_DQ49: U49.H1(DQ4) ; also on sheet 37 38
R_B_DQ50: U49.H7(DQ2) ; also on sheet 37 38
R_B_DQ51: U49.F9(DQ7) ; also on sheet 37 38
R_B_DQ52: U49.G2(DQ1) ; also on sheet 37 38
R_B_DQ53: U49.H3(DQ3) ; also on sheet 37 38
R_B_DQ54: U49.H9(DQ5) ; also on sheet 37 38
R_B_DQ55: U49.G8(DQ0) ; also on sheet 37 38
R_B_DQ56: U50.H3(DQ3) ; also on sheet 37 38
R_B_DQ57: U50.G2(DQ1) ; also on sheet 37 38
R_B_DQ58: U50.H1(DQ4) ; also on sheet 37 38
R_B_DQ59: U50.F1(DQ6) ; also on sheet 37 38
R_B_DQ60: U50.H9(DQ5) ; also on sheet 37 38
R_B_DQ61: U50.F9(DQ7) ; also on sheet 37 38
R_B_DQ62: U50.G8(DQ0) ; also on sheet 37 38
R_B_DQ63: U50.H7(DQ2) ; also on sheet 37 38
R_B_DQS0: U51.F7(DQS) ; also on sheet 38
R_B_DQS1: U52.F7(DQS) ; also on sheet 38
R_B_DQS2: U53.F7(DQS) ; also on sheet 38
R_B_DQS3: U54.F7(DQS) ; also on sheet 38
R_B_DQS4: U47.F7(DQS) ; also on sheet 38
R_B_DQS5: U48.F7(DQS) ; also on sheet 38
R_B_DQS6: U49.F7(DQS) ; also on sheet 38
R_B_DQS7: U50.F7(DQS) ; also on sheet 38
R_B_DQS#0: U51.E8(~{DQS}) ; also on sheet 38
R_B_DQS#1: U52.E8(~{DQS}) ; also on sheet 38
R_B_DQS#2: U53.E8(~{DQS}) ; also on sheet 38
R_B_DQS#3: U54.E8(~{DQS}) ; also on sheet 38
R_B_DQS#4: U47.E8(~{DQS}) ; also on sheet 38
R_B_DQS#5: U48.E8(~{DQS}) ; also on sheet 38
R_B_DQS#6: U49.E8(~{DQS}) ; also on sheet 38
R_B_DQS#7: U50.E8(~{DQS}) ; also on sheet 38
R_B_ODT3: U47.K9(ODT) U48.K9(ODT) U49.K9(ODT) U50.K9(ODT) U51.K9(ODT) U52.K9(ODT) U53.K9(ODT) U54.K9(ODT) ; also on sheet 37
R_B_RAS#: U47.K7(~{RAS}) U48.K7(~{RAS}) U49.K7(~{RAS}) U50.K7(~{RAS}) U51.K7(~{RAS}) U52.K7(~{RAS}) U53.K7(~{RAS}) U54.K7(~{RAS}) ; also on sheet 37 38
R_B_WE#: U47.K3(~{WE}) U48.K3(~{WE}) U49.K3(~{WE}) U50.K3(~{WE}) U51.K3(~{WE}) U52.K3(~{WE}) U53.K3(~{WE}) U54.K3(~{WE}) ; also on sheet 37 38
R_USBP4+: RN34.1(R11) USB4.3
R_USBP4-: RN34.3(R21) USB4.2
R_USBP5+: RN34.5(R31) USB5.3
R_USBP5-: RN34.7(R41) USB5.2
RSMRST#: R286.1 ; also on sheet 17 19 20 21 34 36
USBP4N: RN34.4(R22) ; also on sheet 16
USBP4P: RN34.2(R12) ; also on sheet 16
USBP5N: RN34.8(R42) ; also on sheet 16
USBP5P: RN34.6(R32) ; also on sheet 16
WP-_LAN3: R595.1 U36.3(WP_N)
N113592077: LAN3.9 R279.1
N113595549: LAN3.11 R280.1
N114285409: F6.2 FB30.1
N114285477: F7.2 FB35.1
N115159405: C455.1 FB20.2 FB21.1
N115159407: C454.1 FB22.2 FB23.1
N115159409: C453.1 FB24.2 FB25.1
N115178182: C647.1 R602.2 VGA1.13
N115185766: C646.1 R603.2 VGA1.14
N115261875: C85.1 F9.1 VGA1.9
N115837699: R292.1 U80.B10(NVM_CS)
N115837721: R271.1 R593.2 U80.C9(NVM_SK)
N115837826: C468.1 R276.1 R277.1
N115837828: C469.1 R278.1 R281.1
N115837832: C465.1 R272.1 R275.1
N115837834: C466.1 R273.1 R274.1
N115837900: R291.2 U80.P10(PE_WAKE#)
N115837971: R633.1 U80.N11(SMB_ALRT)
N115838074: R591.2 U80.D3(NVM_SHARED)
N115838386: R283.1 U80.A9(NVM_SI)
N115838442: R637.1 U80.N5(TCK)
N115838444: R635.1 U80.N4(TMS)
N115838446: R636.1 U80.P4(TDI)
N115838628: R634.1 U80.D12(ISOL_TI/PHY_REF)
N115838856: R594.1 R596.1 U80.B5(EN25REG)
N115838938: R284.2 U80.P7(PE_RST#)
N115838954: R815.1 T3.15(MCT0)
N115838978: R817.1 T3.21(MCT2)
N115839004: R282.2 U80.L7(DEVICE_OFF#)
N115839036: C384.2 U80.J14(XTAL2) Y10.2
N115839038: C464.2 U80.K14(XTAL1) Y10.1
N115839088: R285.1 U80.B9(NVM_SO)
N115839220: R286.2 U80.P5(LAN_PWR_GOOD)
N115839251: R590.2 U80.A5(NVM_PROT)
N115839293: C630.2 R815.2 R816.2 R817.2 R818.2
N115839299: R592.2 U80.A13(TEST_EN)
N115839457: R638.1 U80.C6(AUX_PRESENT)
N115839470: R816.1 T3.18(MCT1)
N115839498: R478.2 U80.A6(NVM_TYPE)
N115839513: R818.1 T3.24(MCT3)

Not connected (* = marked no-connect by the designer): LAN3 15(SHELL3)* 16(SHELL4)*; U47 E2(NU/~{RDQS}) R3(NC9) R7(NC10); U48 E2(NU/~{RDQS}) R3(NC9) R7(NC10); U49 E2(NU/~{RDQS}) R3(NC9) R7(NC10); U50 E2(NU/~{RDQS}) R3(NC9) R7(NC10); U51 E2(NU/~{RDQS}) R3(NC9) R7(NC10); U52 E2(NU/~{RDQS}) R3(NC9) R7(NC10); U53 E2(NU/~{RDQS}) R3(NC9) R7(NC10); U54 E2(NU/~{RDQS}) R3(NC9) R7(NC10); U80 A8(SDP0)* A14(TEST16)* B4(NVM_REQ)* B7(NC1)* B8(SDP1)* B12(PHY_HSDACP)* B13(PHY_HSDACN)* B14(PHY_TSTPT)* C3(DOCK_INO)* C7(SDP3)* C8(SDP2)* D10(ISOL_TEX)* D11(NC10)* D14(ISOL_TCK)* E1(NC6)* E3(TEST15)* E11(NC7)* E12(NC8)* H1(TEST0)* H2(TEST1)* H3(TEST2)* J1(TEST3)* J2(TEST4)* J3(TEST5)* J13(NC11)* K1(TEST6)* K12(NC2)* L1(TEST7)* L2(THERMn)* L3(THERMp)* L4(NC9)* L6(NC3)* L8(NC12)* L11(NC4)* L13(LAN_TXD1)* L14(LAN_TXD2)* M1(TEST8)* M3(TEST9)* M5(NC13)* M6(NC5)* M7(NC14)* M8(TEST13)* M9(NC15)* M11(SMB_DATA)* M12(LAN_RXD2)* M13(LAN_RSTAYNC)* M14(LAN_TXD0)* N2(TEST10)* N3(TEST12)* N9(NC16)* N10(PHY_CLK125)* N13(LAN_RXD1)* N14(LAN_CLK)* P1(TEST11)* P6(TDO)* P9(TEST14)* P11(SMB_CLK)* P13(LAN_RXD0)* P14(NC17)*; VGA1 4* 11*

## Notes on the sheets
sheet 39
- 0402
- 0402
sheet 40
- Place close to VGA Connector
- Place close to VGA Connector
- Place close to VGA Connector
